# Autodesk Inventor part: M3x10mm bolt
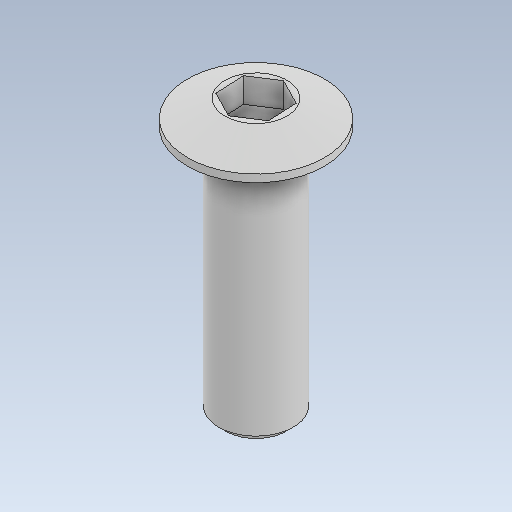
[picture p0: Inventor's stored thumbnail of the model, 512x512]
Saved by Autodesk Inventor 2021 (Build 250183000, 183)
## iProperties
Created: 2023-10
Part Number: M3x10mm bolt
Material: Generico
Document SubType Name: Modeling
Designer: hp
Density: 1 g/cm^3
Appearance: Default
Author: hp
Revision Number: ANY
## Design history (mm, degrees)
feature "Solido1"
body "Solid1"
